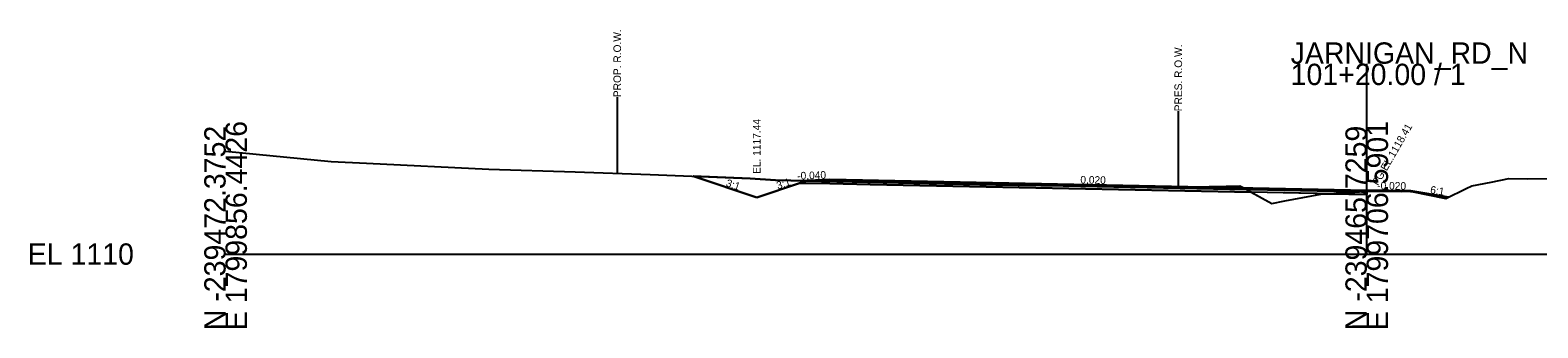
# Model space of a CAD drawing. Extents: x 214513 to 217151, y 214739 to 216780.
# Drawn here: x 215422.7 to 215620.9, y 215738.7 to 215777.8 of the extents above; entities that cross this region are included whole.
import ezdxf

# ---------------------------------------------------------------- set-up
doc = ezdxf.new("R2010")
doc.units = 0
for name, color, linetype in [('CONCEPT - TRANSPORTATION - Roads Text', 7, 'Continuous'), ('DESIGN - CENTERLINE - Proposed', 7, 'Continuous'), ('DESIGN - CENTERLINE - Proposed Text', 7, 'Continuous'), ('DESIGN - DRAINAGE - Special Ditches', 7, 'Continuous'), ('DESIGN - EARTHWORK - Shapes', 7, 'Continuous'), ('DESIGN - ROW - Right-of-Way Linework', 7, 'Continuous'), ('DESIGN - TRANSPORTATION - Text', 7, 'Continuous'), ('DESIGN - TYPICAL - Slope Tie Text', 7, 'Continuous'), ('Section', 7, 'Continuous'), ('SURVEY - DTM GRAPHICS - Triangles', 7, 'Continuous'), ('SURVEY - PROPERTY - ROW Lines', 7, 'Continuous'), ('XSCell', 7, 'Continuous')]:
    doc.layers.add(name, color=color, linetype=linetype)

msp = doc.modelspace()

# ---------------------------------------------------------------- linework, layer by layer
at = {"layer": 'DESIGN - DRAINAGE - Special Ditches'}
for points in [[(215518.18, 215755.81), (215509.84, 215758.59)], [(215524.97, 215758.07), (215518.18, 215755.81)], [(215527.78, 215758.19), (215527.78, 215757.94), (215533.07, 215757.83), (215598.36, 215756.52), (215598.36, 215756.19), (215533.07, 215757.5), (215527.78, 215757.61), (215523.81, 215757.69), (215524.97, 215758.07), (215527.78, 215758.19)], [(215527.78, 215758.19), (215598.36, 215756.77), (215598.36, 215756.67), (215598.36, 215756.67), (215527.78, 215758.09), (215527.78, 215758.09), (215527.78, 215758.19), (215527.78, 215758.19)], [(215527.78, 215758.09), (215598.36, 215756.67), (215598.36, 215756.52), (215598.36, 215756.52), (215527.78, 215757.94), (215527.78, 215757.94), (215527.78, 215758.09), (215527.78, 215758.09), (215527.78, 215758.09)], [(215598.36, 215756.77), (215598.36, 215756.77), (215598.36, 215756.67), (215598.36, 215756.67), (215598.36, 215756.67), (215604.17, 215756.56), (215604.17, 215756.56), (215604.17, 215756.66), (215598.36, 215756.77)], [(215604.17, 215756.66), (215609.1, 215755.84)]]:
    msp.add_lwpolyline(points, dxfattribs=at)
at = {"layer": 'DESIGN - EARTHWORK - Shapes'}
for p, q in [((215509.84, 215758.59), (215518.18, 215755.81)), ((215518.18, 215755.81), (215523.81, 215757.69)), ((215523.81, 215757.69), (215524.68, 215757.97)), ((215524.68, 215757.97), (215523.81, 215757.69)), ((215582.56, 215756.84), (215558.61, 215757.32)), ((215558.61, 215757.32), (215582.56, 215756.84)), ((215577.64, 215757.19), (215575.13, 215757.14)), ((215582.26, 215757), (215575.13, 215757.14)), ((215575.13, 215757.14), (215582.26, 215757)), ((215577.64, 215757.19), (215582.05, 215757.1)), ((215582.05, 215757.1), (215577.64, 215757.19)), ((215582.26, 215757), (215582.05, 215757.1)), ((215583.18, 215756.5), (215582.56, 215756.84)), ((215593.63, 215756.29), (215583.18, 215756.5)), ((215593.63, 215756.29), (215598.36, 215756.19)), ((215598.36, 215756.58), (215597.67, 215756.54)), ((215597.67, 215756.54), (215598.36, 215756.52)), ((215598.36, 215756.67), (215598.36, 215756.58)), ((215602.99, 215756.58), (215598.36, 215756.67)), ((215598.36, 215756.52), (215598.36, 215756.58)), ((215604.17, 215756.66), (215604.17, 215756.58)), ((215609.1, 215755.84), (215604.17, 215756.66))]:
    msp.add_line(p, q, dxfattribs=at)
for points in [[(215524.68, 215757.97), (215520.65, 215758.06), (215517.32, 215758.28), (215509.84, 215758.59)], [(215523.81, 215757.69), (215527.78, 215757.61), (215533.07, 215757.5), (215583.18, 215756.5)], [(215558.61, 215757.32), (215549.59, 215757.46), (215545.34, 215757.52), (215542.88, 215757.58), (215524.68, 215757.97)], [(215575.13, 215757.14), (215573.16, 215757.1), (215558.61, 215757.32)], [(215582.05, 215757.1), (215581.68, 215757.29), (215578.1, 215757.2), (215577.64, 215757.19)], [(215582.56, 215756.84), (215582.54, 215756.85), (215582.26, 215757)], [(215583.18, 215756.5), (215585.87, 215755.01), (215587.6, 215755.35), (215592.34, 215756.22), (215593.63, 215756.29)], [(215597.67, 215756.54), (215595.01, 215756.37), (215593.63, 215756.29)], [(215598.36, 215756.19), (215598.36, 215756.52), (215597.67, 215756.54)], [(215598.36, 215756.58), (215598.65, 215756.6), (215602.99, 215756.58)], [(215604.17, 215756.58), (215604.23, 215756.57), (215608.76, 215755.67), (215609.1, 215755.84)]]:
    msp.add_lwpolyline(points, dxfattribs=at)
at = {"layer": 'DESIGN - ROW - Right-of-Way Linework'}
msp.add_lwpolyline([(215499.84, 215768.97), (215499.84, 215758.97)], dxfattribs=at)
at = {"layer": 'SURVEY - DTM GRAPHICS - Triangles'}
msp.add_lwpolyline([(215448.36, 215761.86), (215462.23, 215760.53), (215466.87, 215760.29), (215482.95, 215759.51), (215494.31, 215759.17), (215504.19, 215758.82), (215517.32, 215758.28), (215520.65, 215758.06), (215542.88, 215757.58), (215545.34, 215757.52), (215549.59, 215757.46), (215573.16, 215757.1), (215578.1, 215757.2), (215581.68, 215757.29), (215582.54, 215756.85), (215585.87, 215755.01), (215587.6, 215755.35), (215592.34, 215756.22), (215595.01, 215756.37), (215598.65, 215756.6), (215604.1, 215756.58), (215604.17, 215756.58), (215604.23, 215756.57), (215608.76, 215755.67), (215611.43, 215756.98), (215612.19, 215757.34), (215614.71, 215757.82), (215617.04, 215758.29), (215619.54, 215758.23), (215632, 215758.38)], dxfattribs=at)
at = {"layer": 'SURVEY - PROPERTY - ROW Lines'}
msp.add_lwpolyline([(215573.59, 215767.11), (215573.59, 215757.11)], dxfattribs=at)
at = {"layer": 'XSCell'}
for p, q in [((215598.36, 215748.36), (215598.36, 215773.36)), ((215448.36, 215748.36), (215598.36, 215748.36)), ((215598.36, 215748.36), (215748.36, 215748.36))]:
    msp.add_line(p, q, dxfattribs=at)

# ---------------------------------------------------------------- texts
at = {"layer": 'CONCEPT - TRANSPORTATION - Roads Text'}
for s, rotation, p in [('-0.040', 2.2906, (215523.52, 215758.12)), ('0.020', 358.8542, (215560.71, 215757.63)), ('-0.020', 358.8542, (215599.73, 215756.87))]:
    msp.add_text(s, height=1, rotation=rotation, dxfattribs=at).set_placement(p)
at = {"layer": 'DESIGN - CENTERLINE - Proposed'}
msp.add_text('EL. 1117.44', height=1, rotation=90, dxfattribs=at).set_placement((215518.68, 215758.89))
at = {"layer": 'DESIGN - CENTERLINE - Proposed Text'}
msp.add_text('FG EL.1118.41', height=1, rotation=60, dxfattribs=at).set_placement((215599.86, 215757.27))
at = {"layer": 'DESIGN - TRANSPORTATION - Text'}
for s, p in [('PROP. R.O.W.', (215500.34, 215768.97)), ('PRES. R.O.W.', (215574.09, 215767.11))]:
    msp.add_text(s, height=1, rotation=90, dxfattribs=at).set_placement(p)
at = {"layer": 'DESIGN - TYPICAL - Slope Tie Text'}
for s, rotation, p in [('3:1', 341.5651, (215514.04, 215757.29)), ('3:1', 18.4349, (215520.96, 215756.84)), ('6:1', 350.5377, (215606.65, 215756.35))]:
    msp.add_text(s, height=1, rotation=rotation, dxfattribs=at).set_placement(p)
at = {"layer": 'Section'}
msp.add_text('-', height=0.0001, dxfattribs=at).set_placement((215448.36, 215748.36))
at = {"layer": 'XSCell'}
for s, p in [('JARNIGAN_RD_N', (215588.36, 215773.36)), ('101+20.00 / 1', (215588.36, 215770.56)), ('EL 1110', (215422.36, 215746.96))]:
    msp.add_text(s, height=2.8, dxfattribs=at).set_placement(p)
for s, p in [('E 1799856.4426', (215451.16, 215738.36)), ('E 1799706.5901', (215601.16, 215738.36)), ('N -239472.3752', (215448.36, 215738.36)), ('N -239465.7259', (215598.36, 215738.36))]:
    msp.add_text(s, height=2.8, rotation=90, dxfattribs=at).set_placement(p)

doc.saveas('drawing.dxf')
